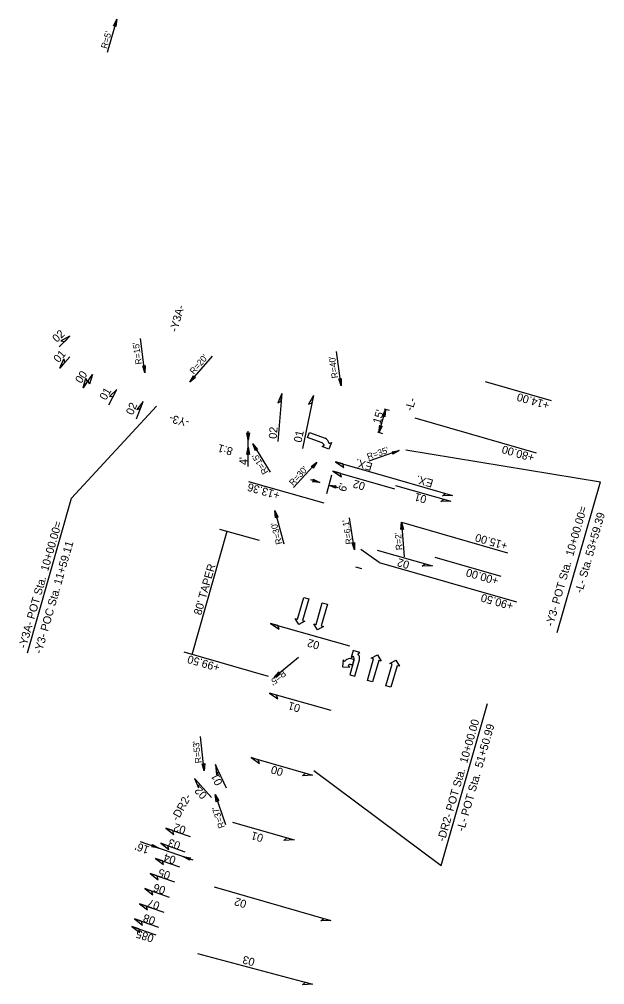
# Model space of a CAD drawing. Extents: x 2096941 to 2098098, y 685096 to 689626.
# Drawn here: x 2097712 to 2098078, y 689023 to 689626 of the extents above; entities that cross this region are included whole.
import ezdxf

# ---------------------------------------------------------------- set-up
doc = ezdxf.new("R2010")
doc.units = 0
for name, color, linetype in [('Prop Dimension', 7, 'Continuous'), ('Prop Dimension Text', 7, 'Continuous'), ('Prop Horizontal Alignment Direction Label', 7, 'Continuous'), ('Prop Horizontal Alignment Station Label', 7, 'Continuous'), ('Prop Lane Arrow CELL', 7, 'Continuous'), ('Prop Superelevation  Arrow CELL', 7, 'Continuous'), ('Prop Superelevation Label', 7, 'Continuous'), ('Prop Terminator CELL', 7, 'Continuous')]:
    doc.layers.add(name, color=color, linetype=linetype)

msp = doc.modelspace()

# ---------------------------------------------------------------- linework, layer by layer
at = {"layer": 'Prop Dimension'}
for p, q in [((2097773.09, 689626.1), (2097767.14, 689605.33)), ((2097790.75, 689405.41), (2097787.9, 689426.83)), ((2097818.73, 689399.52), (2097833, 689415.75)), ((2097913.27, 689397.27), (2097910.41, 689418.69)), ((2098003.34, 689399.91), (2098044.63, 689388.09)), ((2097941.11, 689382.4), (2097936.96, 689367.99)), ((2097943.5, 689381.72), (2097940.34, 689382.62)), ((2097959.37, 689377.13), (2098035.27, 689355.4)), ((2097855.33, 689346.82), (2097855.2, 689368.98)), ((2097939.37, 689367.3), (2097936.22, 689368.2)), ((2097858.09, 689360.92), (2097868.92, 689343.29)), ((2097949.66, 689356.78), (2097930.57, 689350.25)), ((2097898.25, 689349.61), (2097883.6, 689333.73)), ((2097855.49, 689337.55), (2097902.57, 689324.07)), ((2097900, 689336.87), (2097894.33, 689338.5)), ((2097907.41, 689341.35), (2097904.09, 689329.77)), ((2097905.66, 689335.25), (2097911.33, 689333.62)), ((2097871.99, 689319.38), (2097877.45, 689298.47)), ((2097921.66, 689294.83), (2097918.56, 689314.78)), ((2097951.08, 689312.02), (2097952.65, 689290.47)), ((2097951.08, 689312.02), (2098017.38, 689292.92)), ((2097820.21, 689229.47), (2097842.23, 689306.38)), ((2097837.34, 689307.78), (2097862.03, 689300.71)), ((2097937.16, 689286.9), (2097925.75, 689294.95)), ((2097971.92, 689290.17), (2098013.22, 689278.35)), ((2097922.29, 689284.22), (2097926.16, 689283.11)), ((2097937.16, 689286.9), (2098022.88, 689262.31)), ((2097814.97, 689230.97), (2097867.84, 689215.83)), ((2097871.32, 689215.13), (2097886.7, 689227.64)), ((2097827.84, 689156.77), (2097825.43, 689178.24)), ((2097834.6, 689141.96), (2097841.03, 689123.2)), ((2097787.79, 689112.54), (2097820.62, 689101.11))]:
    msp.add_line(p, q, dxfattribs=at)
at = {"layer": 'Prop Horizontal Alignment Station Label'}
for p, q in [((2097798.02, 689384.44), (2097744.95, 689326.95)), ((2097953.7, 689357.31), (2098075.31, 689337.19)), ((2098048.41, 689243.23), (2098075.31, 689337.19)), ((2097717.3, 689230.35), (2097744.95, 689326.95)), ((2097975.77, 689097.68), (2098004.73, 689198.82)), ((2097896.34, 689156.96), (2097975.77, 689097.68))]:
    msp.add_line(p, q, dxfattribs=at)
at = {"layer": 'Prop Lane Arrow CELL'}
for p, q in [((2097892.34, 689365.03), (2097893.49, 689368.12)), ((2097893.49, 689368.12), (2097903.37, 689364.41)), ((2097900.9, 689361.82), (2097892.34, 689365.03)), ((2097907.22, 689361.85), (2097905.72, 689357.71)), ((2097905.86, 689361.23), (2097907.22, 689361.85)), ((2097901.49, 689359.25), (2097902.84, 689359.86)), ((2097905.72, 689357.71), (2097901.49, 689359.25)), ((2097886.09, 689251.55), (2097889.95, 689265.01)), ((2097893.12, 689264.1), (2097889.27, 689250.64)), ((2097889.95, 689265.01), (2097893.12, 689264.1)), ((2097897.74, 689248.22), (2097901.59, 689261.68)), ((2097904.76, 689260.77), (2097900.91, 689247.31)), ((2097901.59, 689261.68), (2097904.76, 689260.77)), ((2097886.86, 689248.05), (2097884.65, 689251.96)), ((2097884.65, 689251.96), (2097886.09, 689251.55)), ((2097890.71, 689250.23), (2097886.86, 689248.05)), ((2097889.27, 689250.64), (2097890.71, 689250.23)), ((2097898.51, 689244.72), (2097896.3, 689248.63)), ((2097896.3, 689248.63), (2097897.74, 689248.22)), ((2097902.35, 689246.9), (2097898.51, 689244.72)), ((2097900.91, 689247.31), (2097902.35, 689246.9)), ((2097920.87, 689231.89), (2097919.58, 689227.57)), ((2097919.58, 689227.57), (2097920.88, 689228.29)), ((2097925.08, 689230.63), (2097920.87, 689231.89)), ((2097923.79, 689229.91), (2097925.08, 689230.63)), ((2097932.19, 689227.06), (2097936.04, 689229.23)), ((2097936.04, 689229.23), (2097938.25, 689225.32)), ((2097914.55, 689226.11), (2097914.27, 689221.72)), ((2097914.27, 689221.72), (2097918.76, 689221.44)), ((2097915.48, 689225.07), (2097914.55, 689226.11)), ((2097918.76, 689221.44), (2097917.66, 689222.63)), ((2097921.3, 689225.57), (2097918.78, 689216.78)), ((2097920.41, 689222.49), (2097921.32, 689225.67)), ((2097921.95, 689215.87), (2097924.86, 689226.01)), ((2097929.78, 689213.18), (2097933.63, 689226.64)), ((2097933.63, 689226.64), (2097932.19, 689227.06)), ((2097936.8, 689225.73), (2097932.95, 689212.28)), ((2097938.25, 689225.32), (2097936.8, 689225.73)), ((2097941.32, 689209.88), (2097945.17, 689223.34)), ((2097943.73, 689223.75), (2097947.57, 689225.93)), ((2097945.17, 689223.34), (2097943.73, 689223.75)), ((2097948.34, 689222.43), (2097944.49, 689208.97)), ((2097947.57, 689225.93), (2097949.78, 689222.02)), ((2097949.78, 689222.02), (2097948.34, 689222.43)), ((2097918.78, 689216.78), (2097921.95, 689215.87)), ((2097932.95, 689212.28), (2097929.78, 689213.18)), ((2097944.49, 689208.97), (2097941.32, 689209.88))]:
    msp.add_line(p, q, dxfattribs=at)
for points in [[(2097921.32, 689225.67), (2097921.43, 689226.04), (2097921.12, 689226.18), (2097920.44, 689226.5), (2097919.71, 689226.78), (2097918.88, 689226.88)], [(2097919.23, 689223.26), (2097919.82, 689223.13), (2097920.23, 689222.92), (2097920.38, 689222.79), (2097920.41, 689222.49)]]:
    msp.add_lwpolyline(points, dxfattribs=at)
for centre, radius, start, end in [((2097899.77, 689358.76), 3.28, 19.77586, 69.43404), ((2097900.81, 689359.85), 5.25, 15.44627, 60.75797), ((2097918.17, 689226.48), 3.28, 344.02589, 33.68406), ((2097919.66, 689226.68), 5.25, 352.70196, 38.01366)]:
    msp.add_arc(centre, radius, start, end, dxfattribs=at)
for centre, major_axis, ratio, start_param, end_param in [((2097919.41, 689221.88), (-3.91, 3.22), 0.985216, 5.500082, 6.29092), ((2097919.13, 689221.26), (-2.01, 0.11), 0.993893, 4.712389, 5.579088)]:
    msp.add_ellipse(centre, major_axis=major_axis, ratio=ratio, start_param=start_param, end_param=end_param, dxfattribs=at)
at = {"layer": 'Prop Superelevation  Arrow CELL'}
for p, q in [((2097743.88, 689428.15), (2097737.24, 689421.54)), ((2097737.5, 689408.31), (2097743.78, 689415.35)), ((2097752.1, 689395.87), (2097757.91, 689404.22)), ((2097768.16, 689385.23), (2097773.26, 689394.85)), ((2097876.24, 689392.36), (2097873.7, 689362.47)), ((2097896.16, 689391.12), (2097889.28, 689357.98)), ((2097785.46, 689376.55), (2097789.63, 689387.39)), ((2097909.9, 689349.68), (2097948.36, 689338.67)), ((2097908.25, 689343.91), (2097946.71, 689332.9)), ((2097948.36, 689338.67), (2097982.97, 689328.76)), ((2097947.32, 689335.04), (2097981.93, 689325.13)), ((2097935.76, 689294.66), (2097970.37, 689284.75)), ((2097869.3, 689248.84), (2097918.61, 689234.73)), ((2097907.05, 689194.35), (2097868.59, 689205.36)), ((2097857.03, 689164.98), (2097895.49, 689153.97)), ((2097834.73, 689160.63), (2097841.48, 689146.12)), ((2097821.66, 689152), (2097832.36, 689140.09)), ((2097803.88, 689120.95), (2097818.99, 689115.69)), ((2097845.47, 689124.6), (2097883.93, 689113.59)), ((2097800.59, 689111.51), (2097815.7, 689106.25)), ((2097797.31, 689102.07), (2097812.42, 689096.81)), ((2097794.02, 689092.62), (2097809.13, 689087.36)), ((2097790.73, 689083.18), (2097805.84, 689077.92)), ((2097833.92, 689084.22), (2097906.89, 689063.33)), ((2097787.41, 689073.75), (2097802.52, 689068.49)), ((2097782.51, 689059.57), (2097797.62, 689054.31)), ((2097784.16, 689064.29), (2097799.27, 689059.03)), ((2097823.52, 689042.77), (2097895.52, 689023.58))]:
    msp.add_line(p, q, dxfattribs=at)
for points in [[(2097743.88, 689428.15), (2097738.22, 689425.33), (2097740.6, 689424.88)], [(2097737.5, 689408.31), (2097740, 689414.12), (2097740.58, 689411.76)], [(2097757.91, 689404.22), (2097756.12, 689398.15), (2097755.26, 689400.42)], [(2097752.1, 689395.87), (2097753.89, 689401.94), (2097754.74, 689399.67)], [(2097773.26, 689394.85), (2097768.69, 689390.49), (2097771.1, 689390.76)], [(2097876.24, 689392.36), (2097873.74, 689386.55), (2097875.85, 689387.75)], [(2097896.16, 689391.12), (2097892.98, 689385.65), (2097895.22, 689386.59)], [(2097789.63, 689387.39), (2097785.61, 689382.51), (2097787.97, 689383.07)], [(2097909.9, 689349.68), (2097915.12, 689346.1), (2097914.35, 689348.41)], [(2097908.25, 689343.91), (2097913.47, 689340.34), (2097912.7, 689342.64)], [(2097982.97, 689328.76), (2097976.65, 689328.49), (2097978.52, 689330.04)], [(2097981.93, 689325.13), (2097975.61, 689324.86), (2097977.48, 689326.4)], [(2097970.37, 689284.75), (2097964.05, 689284.48), (2097965.92, 689286.02)], [(2097869.3, 689248.84), (2097874.52, 689245.26), (2097873.75, 689247.57)], [(2097868.59, 689205.36), (2097873.81, 689201.78), (2097873.04, 689204.08)], [(2097857.03, 689164.98), (2097862.25, 689161.4), (2097861.48, 689163.7)], [(2097834.74, 689160.62), (2097835.45, 689154.34), (2097836.69, 689156.43)], [(2097895.49, 689153.97), (2097889.17, 689153.7), (2097891.04, 689155.24)], [(2097821.66, 689152), (2097824.19, 689146.2), (2097824.75, 689148.56)], [(2097803.88, 689120.95), (2097808.89, 689117.09), (2097808.25, 689119.43)], [(2097883.93, 689113.59), (2097877.61, 689113.32), (2097879.48, 689114.86)], [(2097800.59, 689111.51), (2097805.6, 689107.65), (2097804.96, 689109.99)], [(2097797.31, 689102.07), (2097802.32, 689098.2), (2097801.67, 689100.54)], [(2097794.02, 689092.62), (2097799.03, 689088.76), (2097798.39, 689091.1)], [(2097790.73, 689083.18), (2097795.74, 689079.32), (2097795.1, 689081.66)], [(2097787.41, 689073.75), (2097792.41, 689069.88), (2097791.77, 689072.23)], [(2097782.51, 689059.57), (2097787.52, 689055.71), (2097786.88, 689058.05)], [(2097784.16, 689064.29), (2097789.16, 689060.43), (2097788.52, 689062.77)], [(2097906.89, 689063.33), (2097900.57, 689063.06), (2097902.44, 689064.6)], [(2097895.52, 689023.58), (2097889.21, 689023.19), (2097891.05, 689024.77)]]:
    msp.add_lwpolyline(points, close=True, dxfattribs=at)
at = {"layer": 'Prop Terminator CELL'}
for points in [[(2097771.1, 689621.99), (2097773.09, 689626.1), (2097772.61, 689621.53), (2097772, 689622.31)], [(2097790.92, 689409.97), (2097790.75, 689405.41), (2097789.36, 689409.79), (2097790.23, 689409.32)], [(2097822.28, 689402.39), (2097818.73, 689399.52), (2097821.11, 689403.45), (2097821.34, 689402.49)], [(2097913.44, 689401.83), (2097913.27, 689397.27), (2097911.88, 689401.65), (2097912.74, 689401.19)], [(2097939.1, 689378.3), (2097941.11, 689382.4), (2097940.61, 689377.84), (2097940, 689378.61)], [(2097938.97, 689372.09), (2097936.96, 689367.99), (2097937.46, 689372.56), (2097938.07, 689371.78)], [(2097855.99, 689367.78), (2097855.24, 689363.27), (2097854.41, 689367.79), (2097855.21, 689367.22)], [(2097859.78, 689356.68), (2097858.09, 689360.92), (2097861.14, 689357.48), (2097860.16, 689357.55)], [(2097854.51, 689354.31), (2097855.26, 689358.81), (2097856.08, 689354.29), (2097855.28, 689354.86)], [(2097945.15, 689356.06), (2097949.66, 689356.78), (2097945.64, 689354.56), (2097945.92, 689355.5)], [(2097894.63, 689346.83), (2097898.25, 689349.61), (2097895.77, 689345.74), (2097895.57, 689346.71)], [(2097895.88, 689338.84), (2097900, 689336.87), (2097895.43, 689337.33), (2097896.2, 689337.94)], [(2097909.78, 689333.28), (2097905.66, 689335.25), (2097910.24, 689334.79), (2097909.46, 689334.17)], [(2097872.37, 689314.83), (2097871.99, 689319.38), (2097873.9, 689315.2), (2097872.98, 689315.56)], [(2097950.63, 689307.47), (2097951.08, 689312.02), (2097952.21, 689307.56), (2097951.37, 689308.08)], [(2097921.74, 689299.39), (2097921.66, 689294.83), (2097920.18, 689299.17), (2097921.05, 689298.73)], [(2097874.32, 689218.57), (2097871.32, 689215.13), (2097875.34, 689217.36), (2097874.39, 689217.62)], [(2097828.11, 689161.33), (2097827.84, 689156.77), (2097826.54, 689161.18), (2097827.4, 689160.7)], [(2097835.33, 689137.45), (2097834.6, 689141.96), (2097836.83, 689137.94), (2097835.88, 689138.22)], [(2097795.54, 689110.67), (2097799.53, 689108.45), (2097794.99, 689109.19), (2097795.8, 689109.75)], [(2097818.64, 689100.98), (2097814.64, 689103.19), (2097819.18, 689102.46), (2097818.37, 689101.9)]]:
    msp.add_lwpolyline(points, close=True, dxfattribs=at)

# ---------------------------------------------------------------- texts
at = {"layer": 'Prop Dimension Text'}
for s, height, rotation, p in [("R=5'", 4, 74.02589, (2097766.99, 689607.43)), ("R=15'", 4, 98.35201, (2097788.94, 689410.83)), ("R=20'", 4, 49.43401, (2097821.31, 689404.08)), ("R=40'", 4, 98.35201, (2097911.52, 689402.21)), ('+14.00', 5, 164.02589, (2098043.88, 689387.14)), ("15'", 5, 73.74204, (2097937.77, 689373.03)), ('8:1', 5, 164.02589, (2097846.08, 689358.33)), ("R=35'", 4, 18.86536, (2097930.29, 689350.92)), ('+80.00', 5, 164.02589, (2098034.5, 689354.46)), ("4'", 5, 90.31257, (2097854.79, 689347.73)), ("R=15'", 4, 121.56694, (2097867.99, 689343.42)), ("R=30'", 4, 47.30212, (2097883.34, 689334.51)), ('+13.36', 5, 164.02589, (2097875.52, 689330.86)), ("6'", 5, 73.74204, (2097916.14, 689330.68)), ("R=6.1'", 4, 98.8305, (2097920.36, 689298.47)), ("R=30'", 4, 104.65291, (2097876.65, 689298.68)), ("R=2'", 4, 94.16905, (2097951.62, 689294.74)), ('+15.00', 5, 164.02589, (2098017.82, 689299.31)), ("80' TAPER", 5, 74.02589, (2097825.88, 689253.61)), ('+00.00', 5, 164.02589, (2098012.13, 689277.5)), ('+90.50', 5, 164.02589, (2098021.37, 689261.8)), ('+99.50', 5, 164.02589, (2097838.02, 689223.37)), ("R=5'", 4, 219.8701, (2097876.86, 689219.88)), ("R=53'", 4, 97.17525, (2097826.2, 689161.75)), ("R=37'", 4, 108.90863, (2097840.79, 689121.66)), ("16'", 5, 160.80523, (2097793.92, 689109.35))]:
    msp.add_text(s, height=height, rotation=rotation, dxfattribs=at).set_placement(p)
at = {"layer": 'Prop Horizontal Alignment Direction Label'}
for s, rotation, p in [('-Y3A-', 74.02589, (2097810.82, 689430.45)), ('-L-', 74.02589, (2097957.92, 689381.1)), ('-Y3-', 166.62018, (2097818.86, 689376.42)), ('-DR2-', 60.9933, (2097811.26, 689125.04))]:
    msp.add_text(s, height=5, rotation=rotation, dxfattribs=at).set_placement(p)
at = {"layer": 'Prop Horizontal Alignment Station Label'}
for s, p in [('-Y3- POT Sta.  10+00.00=', (2098045.72, 689246.54)), ('-L- Sta. 53+59.39', (2098064.01, 689267.44)), ('-Y3A- POT Sta.  10+00.00=', (2097716.4, 689232.87)), ('-Y3- POC Sta. 11+59.11', (2097726.13, 689229.58)), ('-DR2- POT Sta.  10+00.00', (2097978.02, 689112.21)), ('-L- POT Sta.  51+50.99', (2097990.16, 689118.59))]:
    msp.add_text(s, height=5, rotation=74.02589, dxfattribs=at).set_placement(p)
at = {"layer": 'Prop Superelevation Label'}
for s, rotation, p in [('02', 42.98995, (2097735.67, 689423.98)), ('01', 48.31207, (2097736.75, 689411.28)), ('00', 55.18756, (2097750.81, 689398.27)), ('01', 60.17868, (2097766.31, 689387.81)), ('02', 67.05418, (2097783.2, 689378.59)), ('02', 85.1359, (2097873.02, 689363.97)), ('01', 78.26041, (2097888.55, 689361.49)), ('EX.', 163.94122, (2097933.34, 689348.75)), ('02', 163.94122, (2097928.77, 689336.55)), ('EX.', 164.02589, (2097971.32, 689338.39)), ('01', 164.02589, (2097967.18, 689328.38)), ('02', 164.02589, (2097956.4, 689287.48)), ('02', 163.94122, (2097900.26, 689237.18)), ('01', 163.94122, (2097888.26, 689197.94)), ('01', 116.12752, (2097839.46, 689149.16)), ('00', 343.94122, (2097869.01, 689155.32)), ('02', 133.12027, (2097830.02, 689141.9)), ('02', 161.99041, (2097816.73, 689121.78)), ('03', 161.99041, (2097813.35, 689112.13)), ('01', 163.94122, (2097865.14, 689116.86)), ('04', 161.99041, (2097810.5, 689103.05)), ('05', 161.99041, (2097807.07, 689093.48)), ('06', 161.99041, (2097804.04, 689084.16)), ('02', 163.94122, (2097854.64, 689075.67)), ('07', 161.99041, (2097800.42, 689074.54)), ('08', 161.99041, (2097797.7, 689065.18)), ('085', 161.99041, (2097796.74, 689054.09)), ('03', 164.98749, (2097859.78, 689039.45))]:
    msp.add_text(s, height=5, rotation=rotation, dxfattribs=at).set_placement(p)

doc.saveas('drawing.dxf')
